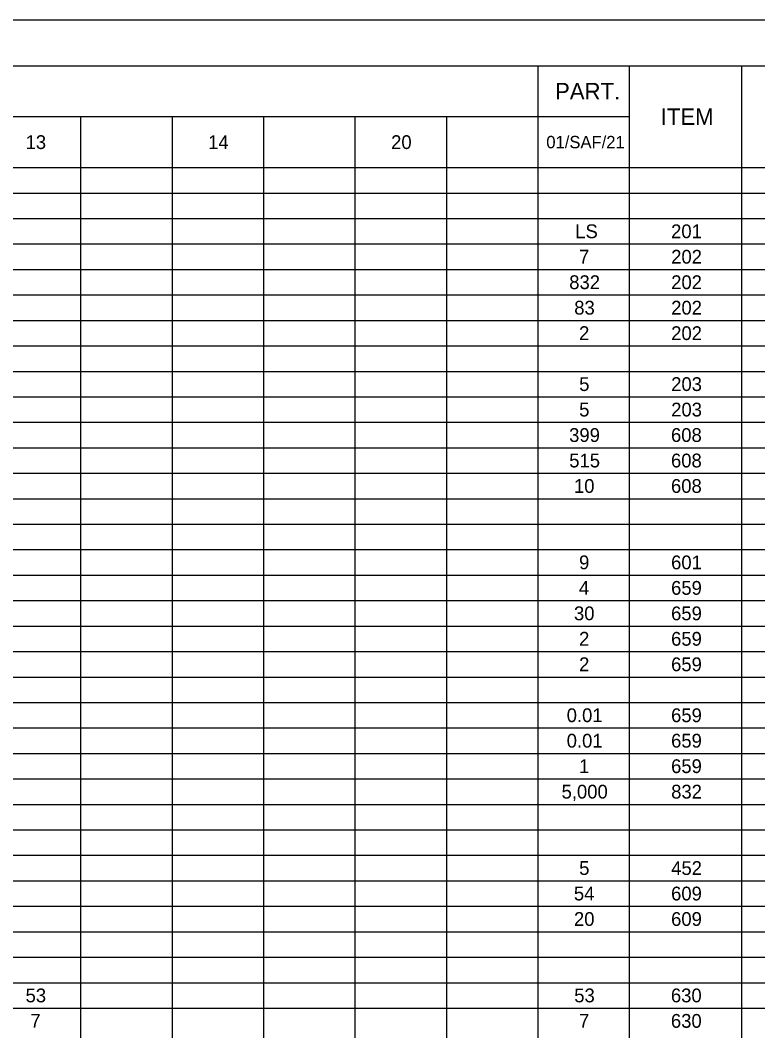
# Model space of a CAD drawing. Extents: x 0 to 34, y 0 to 22.
# Drawn here: x 8.87 to 16.98, y 10.89 to 22 of the extents above; entities that cross this region are included whole.
import ezdxf

# ---------------------------------------------------------------- set-up
doc = ezdxf.new("R2010")
doc.units = 0
for name, color, linetype in [('SH_Border', 7, 'Continuous'), ('SH_Cut_Line', 7, 'Continuous'), ('SH_Text', 7, 'Continuous')]:
    doc.layers.add(name, color=color, linetype=linetype)

msp = doc.modelspace()

# ---------------------------------------------------------------- linework, layer by layer
at = {"layer": 'SH_Border'}
msp.add_lwpolyline([(1.5, 21.5), (33.5, 21.5), (33.5, 0.5), (1.5, 0.5)], close=True, dxfattribs=at)
at = {"layer": 'SH_Cut_Line'}
msp.add_lwpolyline([(0, 0), (34, 0), (34, 22), (0, 22)], close=True, dxfattribs=at)
at = {"layer": 'SH_Text'}
for p, q in [((1.5, 21.5), (32, 21.5)), ((14.56, 21.5), (14.56, 0.5)), ((15.564, 21.5), (15.564, 0.5)), ((16.799, 21.5), (16.799, 0.5)), ((1.5, 20.94), (15.564, 20.94)), ((9.537, 20.94), (9.537, 0.5)), ((10.541, 20.94), (10.541, 0.5)), ((11.546, 20.94), (11.546, 0.5)), ((12.55, 20.94), (12.55, 0.5)), ((13.555, 20.94), (13.555, 0.5)), ((1.5, 20.38), (32, 20.38)), ((1.5, 20.1), (32, 20.1)), ((1.5, 19.82), (32, 19.82)), ((1.5, 19.54), (32, 19.54)), ((1.5, 19.26), (32, 19.26)), ((1.5, 18.98), (32, 18.98)), ((1.5, 18.7), (32, 18.7)), ((1.5, 18.42), (32, 18.42)), ((1.5, 18.14), (32, 18.14)), ((1.5, 17.86), (32, 17.86)), ((1.5, 17.58), (32, 17.58)), ((1.5, 17.3), (32, 17.3)), ((1.5, 17.02), (32, 17.02)), ((1.5, 16.74), (32, 16.74)), ((1.5, 16.46), (32, 16.46)), ((1.5, 16.18), (32, 16.18)), ((1.5, 15.9), (32, 15.9)), ((1.5, 15.62), (32, 15.62)), ((1.5, 15.34), (32, 15.34)), ((1.5, 15.06), (32, 15.06)), ((1.5, 14.78), (32, 14.78)), ((1.5, 14.5), (32, 14.5)), ((1.5, 14.22), (32, 14.22)), ((1.5, 13.94), (32, 13.94)), ((1.5, 13.66), (32, 13.66)), ((1.5, 13.38), (32, 13.38)), ((1.5, 13.1), (32, 13.1)), ((1.5, 12.82), (32, 12.82)), ((1.5, 12.54), (32, 12.54)), ((1.5, 12.26), (32, 12.26)), ((1.5, 11.98), (32, 11.98)), ((1.5, 11.7), (32, 11.7)), ((1.5, 11.42), (32, 11.42)), ((1.5, 11.14), (32, 11.14))]:
    msp.add_line(p, q, dxfattribs=at)

# ---------------------------------------------------------------- texts
for s, height, p in [('PART.', 0.1818, (14.749, 21.129)), ('ITEM', 0.1818, (15.91, 20.849)), ('13', 0.1515, (8.932, 20.584)), ('14', 0.1515, (10.938, 20.584)), ('20', 0.1515, (12.948, 20.584)), ('01/SAF/21', 0.1364, (14.653, 20.592)), ('LS', 0.1515, (14.971, 19.604)), ('201', 0.1515, (16.024, 19.604)), ('7', 0.152, (15.012, 19.324)), ('202', 0.1515, (16.025, 19.324)), ('832', 0.1515, (14.905, 19.044)), ('202', 0.1515, (16.025, 19.044)), ('83', 0.1515, (14.96, 18.764)), ('202', 0.1515, (16.025, 18.764)), ('2', 0.152, (15.013, 18.484)), ('202', 0.1515, (16.025, 18.484)), ('5', 0.152, (15.014, 17.924)), ('203', 0.1515, (16.025, 17.924)), ('5', 0.152, (15.014, 17.644)), ('203', 0.1515, (16.025, 17.644)), ('399', 0.1515, (14.904, 17.364)), ('608', 0.1515, (16.023, 17.364)), ('515', 0.1515, (14.905, 17.084)), ('608', 0.1515, (16.023, 17.084)), ('10', 0.1515, (14.957, 16.804)), ('608', 0.1515, (16.023, 16.804)), ('9', 0.152, (15.013, 15.964)), ('601', 0.1515, (16.024, 15.964)), ('4', 0.152, (15.011, 15.684)), ('659', 0.1515, (16.024, 15.684)), ('30', 0.1515, (14.957, 15.404)), ('659', 0.1515, (16.024, 15.404)), ('2', 0.152, (15.013, 15.124)), ('659', 0.1515, (16.024, 15.124)), ('2', 0.152, (15.013, 14.844)), ('659', 0.1515, (16.024, 14.844)), ('0.01', 0.1515, (14.877, 14.284)), ('659', 0.1515, (16.024, 14.284)), ('0.01', 0.1515, (14.877, 14.004)), ('659', 0.1515, (16.024, 14.004)), ('1', 0.152, (15.013, 13.724)), ('659', 0.1515, (16.024, 13.724)), ('5,000', 0.1515, (14.821, 13.444)), ('832', 0.1515, (16.025, 13.444)), ('5', 0.152, (15.014, 12.604)), ('452', 0.1515, (16.025, 12.604)), ('54', 0.1515, (14.956, 12.324)), ('609', 0.1515, (16.024, 12.324)), ('20', 0.1515, (14.957, 12.044)), ('609', 0.1515, (16.024, 12.044)), ('53', 0.1515, (8.932, 11.204)), ('53', 0.1515, (14.96, 11.204)), ('630', 0.1515, (16.022, 11.204)), ('7', 0.152, (8.985, 10.924)), ('7', 0.152, (15.012, 10.924)), ('630', 0.1515, (16.022, 10.924))]:
    msp.add_text(s, height=height, dxfattribs=at).set_placement(p)

doc.saveas('drawing.dxf')
